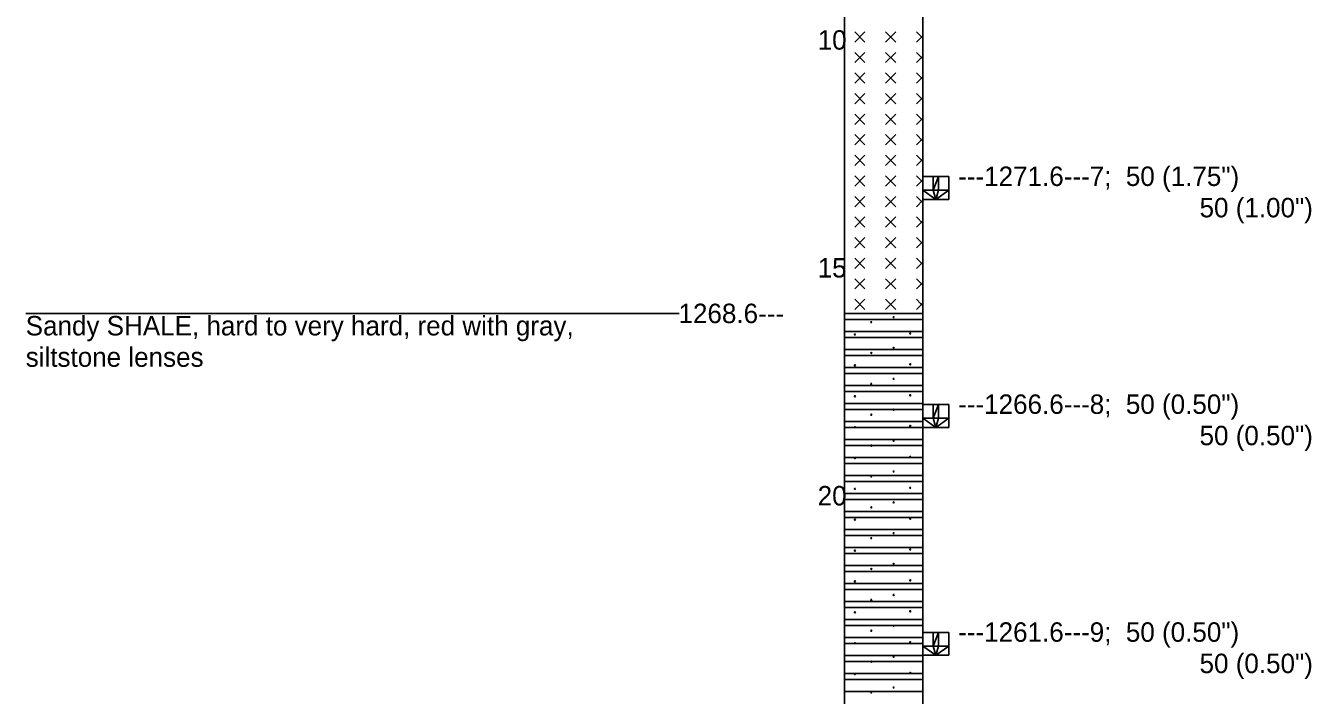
# Model space of a CAD drawing. Extents: x 7 to 126, y 24 to 56.
# Drawn here: x 69.7 to 77.9, y 43.11 to 47.38 of the extents above; entities that cross this region are included whole.
import ezdxf

# ---------------------------------------------------------------- set-up
doc = ezdxf.new("R2010")
doc.units = 0

msp = doc.modelspace()

# ---------------------------------------------------------------- linework, layer by layer
for points in [[(74.9215, 50.1944), (74.9215, 39.1479)], [(75.4215, 50.1944), (75.4215, 39.1479)], [(75.0527, 47.3393), (74.9871, 47.2737)], [(74.9871, 47.3393), (75.0527, 47.2737)], [(75.2495, 47.3393), (75.1839, 47.2737)], [(75.1839, 47.3393), (75.2495, 47.2737)], [(75.3808, 47.3393), (75.4215, 47.2986)], [(75.4215, 47.3144), (75.3808, 47.2737)], [(75.0527, 47.2081), (74.9871, 47.1425)], [(74.9871, 47.2081), (75.0527, 47.1425)], [(75.2495, 47.2081), (75.1839, 47.1425)], [(75.1839, 47.2081), (75.2495, 47.1425)], [(75.3808, 47.2081), (75.4215, 47.1674)], [(75.4215, 47.1832), (75.3808, 47.1425)], [(75.0527, 47.0769), (74.9871, 47.0112)], [(74.9871, 47.0769), (75.0527, 47.0112)], [(75.2495, 47.0769), (75.1839, 47.0112)], [(75.1839, 47.0769), (75.2495, 47.0112)], [(75.3808, 47.0769), (75.4215, 47.0362)], [(75.4215, 47.0519), (75.3808, 47.0112)], [(75.0527, 46.9456), (74.9871, 46.88)], [(74.9871, 46.9456), (75.0527, 46.88)], [(75.2495, 46.9456), (75.1839, 46.88)], [(75.1839, 46.9456), (75.2495, 46.88)], [(75.3808, 46.9456), (75.4215, 46.9049)], [(75.4215, 46.9207), (75.3808, 46.88)], [(75.0527, 46.8144), (74.9871, 46.7488)], [(74.9871, 46.8144), (75.0527, 46.7488)], [(75.2495, 46.8144), (75.1839, 46.7488)], [(75.1839, 46.8144), (75.2495, 46.7488)], [(75.3808, 46.8144), (75.4215, 46.7737)], [(75.4215, 46.7894), (75.3808, 46.7488)], [(75.0527, 46.6832), (74.9871, 46.6175)], [(74.9871, 46.6832), (75.0527, 46.6175)], [(75.2495, 46.6832), (75.1839, 46.6175)], [(75.1839, 46.6832), (75.2495, 46.6175)], [(75.3808, 46.6832), (75.4215, 46.6425)], [(75.4215, 46.6582), (75.3808, 46.6175)], [(75.0527, 46.5519), (74.9871, 46.4863)], [(74.9871, 46.5519), (75.0527, 46.4863)], [(75.2495, 46.5519), (75.1839, 46.4863)], [(75.1839, 46.5519), (75.2495, 46.4863)], [(75.3808, 46.5519), (75.4215, 46.5112)], [(75.4215, 46.527), (75.3808, 46.4863)], [(75.0527, 46.4207), (74.9871, 46.3551)], [(74.9871, 46.4207), (75.0527, 46.3551)], [(75.2495, 46.4207), (75.1839, 46.3551)], [(75.1839, 46.4207), (75.2495, 46.3551)], [(75.3808, 46.4207), (75.4215, 46.38)], [(75.4215, 46.3957), (75.3808, 46.3551)], [(75.4215, 46.4153), (75.5881, 46.4153)], [(75.5881, 46.27), (75.5881, 46.4153)], [(75.0527, 46.2894), (74.9871, 46.2238)], [(74.9871, 46.2894), (75.0527, 46.2238)], [(75.2495, 46.2894), (75.1839, 46.2238)], [(75.1839, 46.2894), (75.2495, 46.2238)], [(75.3808, 46.2894), (75.4215, 46.2488)], [(75.4215, 46.2645), (75.3808, 46.2238)], [(75.4215, 46.27), (75.5881, 46.27)], [(75.0527, 46.1582), (74.9871, 46.0926)], [(74.9871, 46.1582), (75.0527, 46.0926)], [(75.2495, 46.1582), (75.1839, 46.0926)], [(75.1839, 46.1582), (75.2495, 46.0926)], [(75.3808, 46.1582), (75.4215, 46.1175)], [(75.4215, 46.1333), (75.3808, 46.0926)], [(75.0527, 46.027), (74.9871, 45.9614)], [(74.9871, 46.027), (75.0527, 45.9614)], [(75.2495, 46.027), (75.1839, 45.9614)], [(75.1839, 46.027), (75.2495, 45.9614)], [(75.3808, 46.027), (75.4215, 45.9863)], [(75.4215, 46.002), (75.3808, 45.9614)], [(75.0527, 45.8957), (74.9871, 45.8301)], [(74.9871, 45.8957), (75.0527, 45.8301)], [(75.2495, 45.8957), (75.1839, 45.8301)], [(75.1839, 45.8957), (75.2495, 45.8301)], [(75.3808, 45.8957), (75.4215, 45.8551)], [(75.4215, 45.8708), (75.3808, 45.8301)], [(75.0527, 45.7645), (74.9871, 45.6989)], [(74.9871, 45.7645), (75.0527, 45.6989)], [(75.2495, 45.7645), (75.1839, 45.6989)], [(75.1839, 45.7645), (75.2495, 45.6989)], [(75.3808, 45.7645), (75.4215, 45.7238)], [(75.4215, 45.7396), (75.39, 45.7081), (75.3808, 45.6989)], [(75.0527, 45.6333), (74.9871, 45.5677)], [(74.9871, 45.6333), (75.0527, 45.5677)], [(75.2495, 45.6333), (75.1839, 45.5677)], [(75.1839, 45.6333), (75.2495, 45.5677)], [(75.3808, 45.6333), (75.4098, 45.6043), (75.4215, 45.5926)], [(75.4215, 45.6083), (75.411, 45.5979), (75.3808, 45.5677)], [(69.7024, 45.5432), (73.869, 45.5432)], [(74.9215, 45.5432), (75.4215, 45.5432)], [(74.9215, 45.5432), (75.4215, 45.5432)], [(74.9215, 45.5039), (75.4215, 45.5039)], [(75.0965, 45.4874), (75.0949, 45.4903), (75.0916, 45.4903), (75.09, 45.4875), (75.0916, 45.4846), (75.0949, 45.4846), (75.0965, 45.4874)], [(75.2391, 45.5193), (75.2375, 45.5221), (75.2342, 45.5221), (75.2326, 45.5193), (75.2342, 45.5165), (75.2375, 45.5165), (75.2391, 45.5193)], [(74.9215, 45.4284), (75.4215, 45.4284)], [(74.9919, 45.4085), (74.9902, 45.4113), (74.9869, 45.4113), (74.9853, 45.4085), (74.9869, 45.4056), (74.9902, 45.4056), (74.9919, 45.4085)], [(75.3446, 45.415), (75.343, 45.4179), (75.3397, 45.4179), (75.3381, 45.415), (75.3397, 45.4121), (75.343, 45.4121), (75.3446, 45.415)], [(74.9215, 45.3891), (75.4215, 45.3891)], [(75.2391, 45.3224), (75.2375, 45.3253), (75.2342, 45.3253), (75.2326, 45.3224), (75.2342, 45.3196), (75.2375, 45.3196), (75.2391, 45.3224)], [(74.9215, 45.3136), (75.4215, 45.3136)], [(74.9215, 45.2742), (75.4215, 45.2742)], [(75.0965, 45.2906), (75.0949, 45.2934), (75.0916, 45.2934), (75.09, 45.2906), (75.0916, 45.2877), (75.0949, 45.2877), (75.0965, 45.2906)], [(74.9215, 45.1988), (75.4215, 45.1988)], [(74.9215, 45.1594), (75.4215, 45.1594)], [(74.9919, 45.2116), (74.9902, 45.2144), (74.9869, 45.2144), (74.9853, 45.2116), (74.9869, 45.2087), (74.9902, 45.2087), (74.9919, 45.2116)], [(75.3446, 45.2181), (75.343, 45.221), (75.3397, 45.221), (75.3381, 45.2181), (75.3397, 45.2153), (75.343, 45.2153), (75.3446, 45.2181)], [(74.9215, 45.0839), (75.4215, 45.0839)], [(75.0965, 45.0937), (75.0949, 45.0966), (75.0916, 45.0966), (75.09, 45.0938), (75.0916, 45.0909), (75.0949, 45.0909), (75.0965, 45.0937)], [(75.2391, 45.1256), (75.2375, 45.1284), (75.2342, 45.1284), (75.2326, 45.1256), (75.2342, 45.1228), (75.2375, 45.1228), (75.2391, 45.1256)], [(74.9215, 45.0446), (75.4215, 45.0446)], [(74.9919, 45.0148), (74.9902, 45.0176), (74.9869, 45.0176), (74.9853, 45.0148), (74.9869, 45.0119), (74.9902, 45.0119), (74.9919, 45.0148)], [(75.3446, 45.0213), (75.343, 45.0242), (75.3397, 45.0242), (75.3381, 45.0213), (75.3397, 45.0184), (75.343, 45.0184), (75.3446, 45.0213)], [(74.9215, 44.9691), (75.4215, 44.9691)], [(74.9215, 44.9297), (75.4215, 44.9297)], [(75.2391, 44.9287), (75.2375, 44.9316), (75.2342, 44.9316), (75.2326, 44.9287), (75.2342, 44.9259), (75.2375, 44.9259), (75.2391, 44.9287)], [(75.4215, 44.9619), (75.5881, 44.9619)], [(75.5881, 44.8165), (75.5881, 44.9619)], [(74.9215, 44.8543), (75.4215, 44.8543)], [(75.0965, 44.8969), (75.0949, 44.8997), (75.0916, 44.8997), (75.09, 44.8969), (75.0916, 44.894), (75.0949, 44.894), (75.0965, 44.8969)], [(74.9215, 44.8149), (75.4215, 44.8149)], [(74.9919, 44.8179), (74.9902, 44.8207), (74.9869, 44.8207), (74.9853, 44.8179), (74.9869, 44.815), (74.9902, 44.815), (74.9919, 44.8179)], [(75.3446, 44.8244), (75.343, 44.8273), (75.3397, 44.8273), (75.3381, 44.8244), (75.3397, 44.8216), (75.343, 44.8216), (75.3446, 44.8244)], [(75.4215, 44.8165), (75.5881, 44.8165)], [(74.9215, 44.7394), (75.4215, 44.7394)], [(74.9215, 44.7001), (75.4215, 44.7001)], [(75.0965, 44.7), (75.0949, 44.7029), (75.0916, 44.7029), (75.09, 44.7001), (75.0916, 44.6972), (75.0949, 44.6972), (75.0965, 44.7)], [(75.2391, 44.7319), (75.2375, 44.7347), (75.2342, 44.7347), (75.2326, 44.7319), (75.2342, 44.7291), (75.2375, 44.7291), (75.2391, 44.7319)], [(74.9215, 44.6246), (75.4215, 44.6246)], [(74.9215, 44.5852), (75.4215, 44.5852)], [(74.9919, 44.6211), (74.9902, 44.6239), (74.9869, 44.6239), (74.9853, 44.6211), (74.9869, 44.6182), (74.9902, 44.6182), (74.9919, 44.6211)], [(75.3446, 44.6276), (75.343, 44.6305), (75.3397, 44.6305), (75.3381, 44.6276), (75.3397, 44.6247), (75.343, 44.6247), (75.3446, 44.6276)], [(74.9215, 44.5098), (75.4215, 44.5098)], [(75.0965, 44.5032), (75.0949, 44.506), (75.0916, 44.506), (75.09, 44.5032), (75.0916, 44.5003), (75.0949, 44.5003), (75.0965, 44.5032)], [(75.2391, 44.535), (75.2375, 44.5379), (75.2342, 44.5379), (75.2326, 44.535), (75.2342, 44.5322), (75.2375, 44.5322), (75.2391, 44.535)], [(74.9215, 44.4704), (75.4215, 44.4704)], [(74.9919, 44.4242), (74.9902, 44.427), (74.9869, 44.427), (74.9853, 44.4242), (74.9869, 44.4213), (74.9902, 44.4213), (74.9919, 44.4242)], [(75.3446, 44.4307), (75.343, 44.4336), (75.3397, 44.4336), (75.3381, 44.4307), (75.3397, 44.4279), (75.343, 44.4279), (75.3446, 44.4307)], [(74.9215, 44.395), (75.4215, 44.395)], [(74.9215, 44.3556), (75.4215, 44.3556)], [(75.2391, 44.3382), (75.2375, 44.341), (75.2342, 44.341), (75.2326, 44.3382), (75.2342, 44.3354), (75.2375, 44.3354), (75.2391, 44.3382)], [(74.9215, 44.2801), (75.4215, 44.2801)], [(75.0965, 44.3063), (75.0949, 44.3092), (75.0916, 44.3092), (75.09, 44.3064), (75.0916, 44.3035), (75.0949, 44.3035), (75.0965, 44.3063)], [(74.9215, 44.2408), (75.4215, 44.2408)], [(74.9919, 44.2274), (74.9902, 44.2302), (74.9869, 44.2302), (74.9853, 44.2274), (74.9869, 44.2245), (74.9902, 44.2245), (74.9919, 44.2274)], [(75.3446, 44.2339), (75.343, 44.2368), (75.3397, 44.2368), (75.3381, 44.2339), (75.3397, 44.231), (75.343, 44.231), (75.3446, 44.2339)], [(74.9215, 44.1653), (75.4215, 44.1653)], [(74.9215, 44.1259), (75.4215, 44.1259)], [(75.0965, 44.1095), (75.0949, 44.1123), (75.0916, 44.1123), (75.09, 44.1095), (75.0916, 44.1066), (75.0949, 44.1066), (75.0965, 44.1095)], [(75.2391, 44.1413), (75.2375, 44.1442), (75.2342, 44.1442), (75.2326, 44.1413), (75.2342, 44.1385), (75.2375, 44.1385), (75.2391, 44.1413)], [(74.9215, 44.0505), (75.4215, 44.0505)], [(74.9215, 44.0111), (75.4215, 44.0111)], [(74.9919, 44.0305), (74.9902, 44.0333), (74.9869, 44.0333), (74.9853, 44.0305), (74.9869, 44.0276), (74.9902, 44.0276), (74.9919, 44.0305)], [(75.3446, 44.037), (75.343, 44.0399), (75.3397, 44.0399), (75.3381, 44.037), (75.3397, 44.0342), (75.343, 44.0342), (75.3446, 44.037)], [(74.9215, 43.9356), (75.4215, 43.9356)], [(75.2391, 43.9445), (75.2375, 43.9473), (75.2342, 43.9473), (75.2326, 43.9445), (75.2342, 43.9417), (75.2375, 43.9417), (75.2391, 43.9445)], [(74.9215, 43.8963), (75.4215, 43.8963)], [(75.0965, 43.9126), (75.0949, 43.9155), (75.0916, 43.9155), (75.09, 43.9127), (75.0916, 43.9098), (75.0949, 43.9098), (75.0965, 43.9126)], [(74.9215, 43.8208), (75.4215, 43.8208)], [(74.9215, 43.7814), (75.4215, 43.7814)], [(74.9919, 43.8337), (74.9902, 43.8365), (74.9869, 43.8365), (74.9853, 43.8337), (74.9869, 43.8308), (74.9902, 43.8308), (74.9919, 43.8337)], [(75.3446, 43.8402), (75.343, 43.8431), (75.3397, 43.8431), (75.3381, 43.8402), (75.3397, 43.8373), (75.343, 43.8373), (75.3446, 43.8402)], [(74.9215, 43.706), (75.4215, 43.706)], [(75.0965, 43.7158), (75.0949, 43.7186), (75.0916, 43.7186), (75.09, 43.7158), (75.0916, 43.7129), (75.0949, 43.7129), (75.0965, 43.7158)], [(75.2391, 43.7476), (75.2375, 43.7505), (75.2342, 43.7505), (75.2326, 43.7476), (75.2342, 43.7448), (75.2375, 43.7448), (75.2391, 43.7476)], [(74.9215, 43.6666), (75.4215, 43.6666)], [(74.9919, 43.6368), (74.9902, 43.6396), (74.9869, 43.6396), (74.9853, 43.6368), (74.9869, 43.6339), (74.9902, 43.6339), (74.9919, 43.6368)], [(75.3446, 43.6433), (75.343, 43.6462), (75.3397, 43.6462), (75.3381, 43.6433), (75.3397, 43.6405), (75.343, 43.6405), (75.3446, 43.6433)], [(74.9215, 43.5911), (75.4215, 43.5911)], [(74.9215, 43.5518), (75.4215, 43.5518)], [(75.0965, 43.5189), (75.0949, 43.5218), (75.0916, 43.5218), (75.09, 43.519), (75.0916, 43.5161), (75.0949, 43.5161), (75.0965, 43.5189)], [(75.2391, 43.5508), (75.2375, 43.5536), (75.2342, 43.5536), (75.2326, 43.5508), (75.2342, 43.548), (75.2375, 43.548), (75.2391, 43.5508)], [(74.9215, 43.4763), (75.4215, 43.4763)], [(74.9215, 43.437), (75.4215, 43.437)], [(74.9919, 43.44), (74.9902, 43.4428), (74.9869, 43.4428), (74.9853, 43.44), (74.9869, 43.4371), (74.9902, 43.4371), (74.9919, 43.44)], [(75.3446, 43.4465), (75.343, 43.4494), (75.3397, 43.4494), (75.3381, 43.4465), (75.3397, 43.4436), (75.343, 43.4436), (75.3446, 43.4465)], [(75.4215, 43.5084), (75.5881, 43.5084)], [(75.5881, 43.363), (75.5881, 43.5084)], [(74.9215, 43.3615), (75.4215, 43.3615)], [(75.2391, 43.3539), (75.2375, 43.3568), (75.2342, 43.3568), (75.2326, 43.3539), (75.2342, 43.3511), (75.2375, 43.3511), (75.2391, 43.3539)], [(75.4215, 43.363), (75.5881, 43.363)], [(74.9215, 43.3221), (75.4215, 43.3221)], [(75.0965, 43.3221), (75.0949, 43.3249), (75.0916, 43.3249), (75.09, 43.3221), (75.0916, 43.3192), (75.0949, 43.3192), (75.0965, 43.3221)], [(74.9215, 43.2467), (75.4215, 43.2467)], [(74.9215, 43.2073), (75.4215, 43.2073)], [(74.9919, 43.2431), (74.9902, 43.2459), (74.9869, 43.2459), (74.9853, 43.2431), (74.9869, 43.2402), (74.9902, 43.2402), (74.9919, 43.2431)], [(75.3446, 43.2496), (75.343, 43.2525), (75.3397, 43.2525), (75.3381, 43.2496), (75.3397, 43.2468), (75.343, 43.2468), (75.3446, 43.2496)], [(74.9215, 43.1318), (75.4215, 43.1318)], [(75.0965, 43.1252), (75.0949, 43.1281), (75.0916, 43.1281), (75.09, 43.1253), (75.0916, 43.1224), (75.0949, 43.1224), (75.0965, 43.1252)], [(75.2391, 43.1571), (75.2375, 43.1599), (75.2342, 43.1599), (75.2326, 43.1571), (75.2342, 43.1543), (75.2375, 43.1543), (75.2391, 43.1571)]]:
    msp.add_lwpolyline(points)
for points in [[(75.4881, 46.3281), (75.5215, 46.3281), (75.5215, 46.4153), (75.4881, 46.3281)], [(75.4881, 46.3281), (75.5215, 46.4153), (75.4881, 46.4153), (75.4881, 46.3281)], [(75.4881, 46.3281), (75.4215, 46.3281), (75.5048, 46.27), (75.4881, 46.3281)], [(75.4881, 46.3281), (75.5048, 46.27), (75.5215, 46.3281), (75.4881, 46.3281)], [(75.5048, 46.27), (75.5881, 46.3281), (75.5215, 46.3281), (75.5048, 46.27)], [(75.4881, 44.8746), (75.5215, 44.8746), (75.5215, 44.9619), (75.4881, 44.8746)], [(75.4881, 44.8746), (75.5215, 44.9619), (75.4881, 44.9619), (75.4881, 44.8746)], [(75.4881, 44.8746), (75.4215, 44.8746), (75.5048, 44.8165), (75.4881, 44.8746)], [(75.4881, 44.8746), (75.5048, 44.8165), (75.5215, 44.8746), (75.4881, 44.8746)], [(75.5048, 44.8165), (75.5881, 44.8746), (75.5215, 44.8746), (75.5048, 44.8165)], [(75.4881, 43.4212), (75.5215, 43.4212), (75.5215, 43.5084), (75.4881, 43.4212)], [(75.4881, 43.4212), (75.5215, 43.5084), (75.4881, 43.5084), (75.4881, 43.4212)], [(75.4881, 43.4212), (75.4215, 43.4212), (75.5048, 43.363), (75.4881, 43.4212)], [(75.4881, 43.4212), (75.5048, 43.363), (75.5215, 43.4212), (75.4881, 43.4212)], [(75.5048, 43.363), (75.5881, 43.4212), (75.5215, 43.4212), (75.5048, 43.363)]]:
    msp.add_lwpolyline(points, close=True)

# ---------------------------------------------------------------- texts
for s, p in [('10', (74.7511, 47.2254)), ('---1271.6---7;  50 (1.75")', (75.6469, 46.3558)), ('50 (1.00")', (77.1857, 46.1558)), ('15', (74.7511, 45.7719)), ('1268.6---', (73.8641, 45.4812)), ('Sandy SHALE, hard to very hard, red with gray,', (69.7024, 45.4026)), ('siltstone lenses', (69.7024, 45.2026)), ('---1266.6---8;  50 (0.50")', (75.6469, 44.9023)), ('50 (0.50")', (77.1857, 44.7023)), ('20', (74.7511, 44.3185)), ('---1261.6---9;  50 (0.50")', (75.6469, 43.4488)), ('50 (0.50")', (77.1857, 43.2488))]:
    msp.add_text(s, height=0.124).set_placement(p)

doc.saveas('drawing.dxf')
